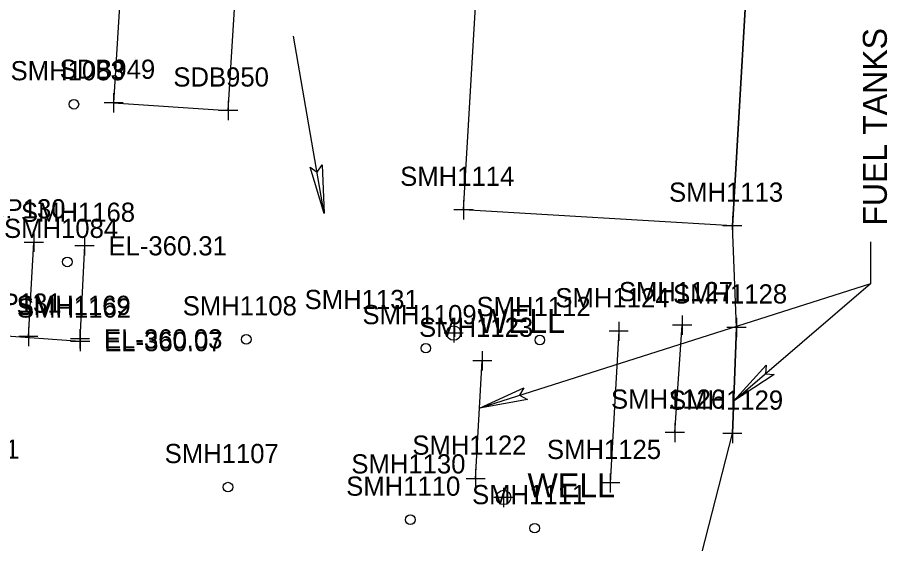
# Model space of a CAD drawing. Extents: x 941041 to 969446, y 397014 to 416764.
# Drawn here: x 951973.7 to 952158, y 402238.2 to 402347.8 of the extents above; entities that cross this region are included whole.
import ezdxf

# ---------------------------------------------------------------- set-up
doc = ezdxf.new("R2010")
doc.units = 0
for name, color, linetype in [('SURVEY - DRAINAGE - Area Shapes Text', 7, 'Continuous'), ('SURVEY - DTM - Spot Points - Locators', 7, 'Continuous'), ('SURVEY - DTM - Spot Points - Point Numbers', 7, 'Continuous'), ('SURVEY - DTM GRAPHICS - Boundary Line', 7, 'Continuous'), ('SURVEY - NON-TRANSPORTATION - Buildings', 7, 'Continuous'), ('SURVEY - NON-TRANSPORTATION - Buildings - Points - Locators', 7, 'Continuous'), ('SURVEY - NON-TRANSPORTATION - Buildings - Points - Numbers', 7, 'Continuous'), ('SURVEY - NON-TRANSPORTATION - Features', 7, 'Continuous'), ('SURVEY - NON-TRANSPORTATION - Features - Points - Locators', 7, 'Continuous'), ('SURVEY - NON-TRANSPORTATION - Features - Points - Numbers', 7, 'Continuous'), ('SURVEY - NON-TRANSPORTATION - Features Text', 7, 'Continuous'), ('SURVEY - TRAFFIC CONTROL - Pavement Marking - Points - Elevations', 7, 'Continuous'), ('SURVEY - TRAFFIC CONTROL - Pavement Marking - Points - Locators', 7, 'Continuous'), ('SURVEY - TRAFFIC CONTROL - Pavement Marking - Points - Numbers', 7, 'Continuous'), ('SURVEY - TRAFFIC CONTROL - Pavement Marking with Text', 7, 'Continuous')]:
    doc.layers.add(name, color=color, linetype=linetype)

msp = doc.modelspace()

# ---------------------------------------------------------------- linework, layer by layer
at = {"layer": 'SURVEY - DRAINAGE - Area Shapes Text'}
msp.add_line((952037.54, 402306.94), (952031.18, 402343.91), dxfattribs=at)
msp.add_lwpolyline([(952037.54, 402306.94), (952034.6, 402316.63), (952036.05, 402315.56), (952037.11, 402317.06)], close=True, dxfattribs=at)
msp.add_lwpolyline([(952037.54, 402306.94), (952034.6, 402316.63), (952036.05, 402315.56), (952037.11, 402317.06), (952037.54, 402306.94)], dxfattribs=at)
at = {"layer": 'SURVEY - DTM - Spot Points - Locators'}
for centre in [(951985.37, 402329.72), (951984, 402296.85), (952021.3, 402280.7), (952082.48, 402280.56), (952058.72, 402278.86), (952017.49, 402249.9), (952055.49, 402243.1), (952081.41, 402241.33)]:
    msp.add_circle(centre, 1, dxfattribs=at)
at = {"layer": 'SURVEY - DTM GRAPHICS - Boundary Line'}
msp.add_lwpolyline([(952174.87, 402139.32), (952134.94, 402138.89), (952111.74, 402140.14), (952111.78, 402142.78), (952111.78, 402144.46), (952111.98, 402146.29), (952112, 402148.65), (952108.15, 402159.38), (952111.19, 402166.81), (952110.92, 402171.67), (952109.38, 402187.17), (952111.97, 402199.03), (952112.01, 402219.6), (952122.62, 402261.05), (952123.48, 402283.18), (952122.61, 402304.4), (952129.97, 402429.37), (952073.92, 402432.67), (952024.1, 402434.31), (951993.79, 402444.97), (951996.33, 402485.31), (951993.88, 402551.9), (951990.9, 402594.94)], dxfattribs=at)
at = {"layer": 'SURVEY - NON-TRANSPORTATION - Buildings'}
for points in [[(952000.14, 402435.7), (951993.65, 402330.03), (952017.51, 402328.41), (952024.1, 402434.31), (952000.14, 402435.7)], [(952122.61, 402304.4), (952066.57, 402307.7), (952073.92, 402432.67), (952129.97, 402429.37), (952122.61, 402304.4)]]:
    msp.add_lwpolyline(points, dxfattribs=at)
at = {"layer": 'SURVEY - NON-TRANSPORTATION - Buildings - Points - Locators'}
for p, q in [((951993.65, 402332.03), (951993.65, 402328.03)), ((951995.65, 402330.03), (951991.65, 402330.03)), ((952017.51, 402330.41), (952017.51, 402326.41)), ((952019.51, 402328.41), (952015.51, 402328.41)), ((952066.57, 402309.7), (952066.57, 402305.7)), ((952068.57, 402307.7), (952064.57, 402307.7)), ((952122.61, 402306.4), (952122.61, 402302.4)), ((952124.61, 402304.4), (952120.61, 402304.4))]:
    msp.add_line(p, q, dxfattribs=at)
at = {"layer": 'SURVEY - NON-TRANSPORTATION - Features'}
for p, q in [((952098.92, 402282.39), (952097.16, 402250.76)), ((952110.62, 402261.25), (952112.15, 402283.66)), ((952123.48, 402283.18), (952122.62, 402261.05)), ((952069.1, 402251.65), (952070.5, 402276.23))]:
    msp.add_line(p, q, dxfattribs=at)
for centre in [(952064.53, 402282.02), (952074.93, 402247.74)]:
    msp.add_circle(centre, 1.5, dxfattribs=at)
at = {"layer": 'SURVEY - NON-TRANSPORTATION - Features - Points - Locators'}
for p, q in [((952112.15, 402285.66), (952112.15, 402281.66)), ((952064.53, 402284.02), (952064.53, 402280.02)), ((952098.92, 402284.39), (952098.92, 402280.39)), ((952123.48, 402285.18), (952123.48, 402281.18)), ((952066.53, 402282.02), (952062.53, 402282.02)), ((952100.92, 402282.39), (952096.92, 402282.39)), ((952114.15, 402283.66), (952110.15, 402283.66)), ((952125.48, 402283.18), (952121.48, 402283.18)), ((952070.5, 402278.23), (952070.5, 402274.23)), ((952072.5, 402276.23), (952068.5, 402276.23)), ((952110.62, 402263.25), (952110.62, 402259.25)), ((952122.62, 402263.05), (952122.62, 402259.05)), ((952112.62, 402261.25), (952108.62, 402261.25)), ((952124.62, 402261.05), (952120.62, 402261.05)), ((952069.1, 402253.65), (952069.1, 402249.65)), ((952097.16, 402252.76), (952097.16, 402248.76)), ((952071.1, 402251.65), (952067.1, 402251.65)), ((952099.16, 402250.76), (952095.16, 402250.76)), ((952074.93, 402249.74), (952074.93, 402245.74)), ((952076.93, 402247.74), (952072.93, 402247.74))]:
    msp.add_line(p, q, dxfattribs=at)
at = {"layer": 'SURVEY - NON-TRANSPORTATION - Features Text'}
for p, q in [((952151.4, 402301.03), (952151.4, 402292.31)), ((952151.4, 402292.31), (952069.95, 402266.39)), ((952151.4, 402292.31), (952122.91, 402267.84))]:
    msp.add_line(p, q, dxfattribs=at)
for points in [[(952122.88, 402267.82), (952129.69, 402275.32), (952129.52, 402273.52), (952131.36, 402273.38)], [(952069.94, 402266.39), (952079.14, 402270.62), (952078.28, 402269.04), (952079.91, 402268.19)]]:
    msp.add_lwpolyline(points, close=True, dxfattribs=at)
for points in [[(952122.88, 402267.82), (952129.69, 402275.32), (952129.52, 402273.52), (952131.36, 402273.38), (952122.88, 402267.82)], [(952069.94, 402266.39), (952079.14, 402270.62), (952078.28, 402269.04), (952079.91, 402268.19), (952069.94, 402266.39)]]:
    msp.add_lwpolyline(points, dxfattribs=at)
at = {"layer": 'SURVEY - TRAFFIC CONTROL - Pavement Marking - Points - Locators'}
for p, q in [((951977.03, 402302.93), (951977.03, 402298.93)), ((951979.03, 402300.93), (951975.03, 402300.93)), ((951987.58, 402302.21), (951987.58, 402298.21)), ((951989.58, 402300.21), (951985.58, 402300.21)), ((951975.89, 402283.27), (951975.89, 402279.27)), ((951986.64, 402282.8), (951986.64, 402278.8)), ((951986.7, 402282.24), (951986.7, 402278.24)), ((951977.89, 402281.27), (951973.89, 402281.27)), ((951988.64, 402280.8), (951984.64, 402280.8)), ((951988.7, 402280.24), (951984.7, 402280.24))]:
    msp.add_line(p, q, dxfattribs=at)
at = {"layer": 'SURVEY - TRAFFIC CONTROL - Pavement Marking with Text'}
for p, q in [((951975.89, 402281.27), (951977.03, 402300.93)), ((951987.58, 402300.21), (951986.64, 402280.8)), ((951986.7, 402280.24), (951916.61, 402285.32))]:
    msp.add_line(p, q, dxfattribs=at)

# ---------------------------------------------------------------- texts
at = {"layer": 'SURVEY - DTM - Spot Points - Point Numbers'}
for s, p in [('SMH1083', (951972.18, 402334.72)), ('SMH1084', (951970.81, 402301.85)), ('SMH1108', (952008.06, 402285.7)), ('SMH1112', (952069.29, 402285.56)), ('SMH1109', (952045.52, 402283.86)), ('SMH1091', (951950.24, 402255.8)), ('SMH1107', (952004.29, 402254.9)), ('SMH1110', (952042.13, 402248.1)), ('SMH1111', (952068.37, 402246.33))]:
    msp.add_text(s, height=4, dxfattribs=at).set_placement(p)
at = {"layer": 'SURVEY - NON-TRANSPORTATION - Buildings - Points - Numbers'}
for s, p in [('SDB949', (951982.4, 402335.03)), ('SDB950', (952006.1, 402333.41)), ('SMH1114', (952053.38, 402312.7)), ('SMH1113', (952109.42, 402309.4))]:
    msp.add_text(s, height=4, dxfattribs=at).set_placement(p)
at = {"layer": 'SURVEY - NON-TRANSPORTATION - Features'}
for p in [(952069.53, 402282.02), (952079.93, 402247.74)]:
    msp.add_text('WELL', height=5, dxfattribs=at).set_placement(p)
at = {"layer": 'SURVEY - NON-TRANSPORTATION - Features - Points - Numbers'}
for s, p in [('SMH1124', (952085.73, 402287.39)), ('SMH1127', (952098.96, 402288.66)), ('SMH1128', (952110.24, 402288.18)), ('SMH1131', (952033.46, 402287.02)), ('SMH1123', (952057.31, 402281.23)), ('SMH1126', (952097.32, 402266.25)), ('SMH1129', (952109.41, 402266.05)), ('SMH1122', (952055.91, 402256.65)), ('SMH1125', (952083.97, 402255.76)), ('SMH1130', (952043.2, 402252.74))]:
    msp.add_text(s, height=4, dxfattribs=at).set_placement(p)
at = {"layer": 'SURVEY - NON-TRANSPORTATION - Features Text'}
msp.add_text('FUEL TANKS', height=4.998, rotation=90, dxfattribs=at).set_placement((952154.81, 402304.4))
at = {"layer": 'SURVEY - TRAFFIC CONTROL - Pavement Marking - Points - Elevations'}
for s, p in [('EL-360.31', (951992.58, 402298.21)), ('EL-360.03', (951991.64, 402278.8)), ('EL-360.07', (951991.7, 402278.24))]:
    msp.add_text(s, height=4, dxfattribs=at).set_placement(p)
at = {"layer": 'SURVEY - TRAFFIC CONTROL - Pavement Marking - Points - Numbers'}
for s, p in [('SP130', (951967.57, 402305.93)), ('SMH1168', (951974.34, 402305.21)), ('SP131', (951966.76, 402286.27)), ('SMH1169', (951973.43, 402285.8)), ('SMH1162', (951973.51, 402285.24))]:
    msp.add_text(s, height=4, dxfattribs=at).set_placement(p)

doc.saveas('drawing.dxf')
